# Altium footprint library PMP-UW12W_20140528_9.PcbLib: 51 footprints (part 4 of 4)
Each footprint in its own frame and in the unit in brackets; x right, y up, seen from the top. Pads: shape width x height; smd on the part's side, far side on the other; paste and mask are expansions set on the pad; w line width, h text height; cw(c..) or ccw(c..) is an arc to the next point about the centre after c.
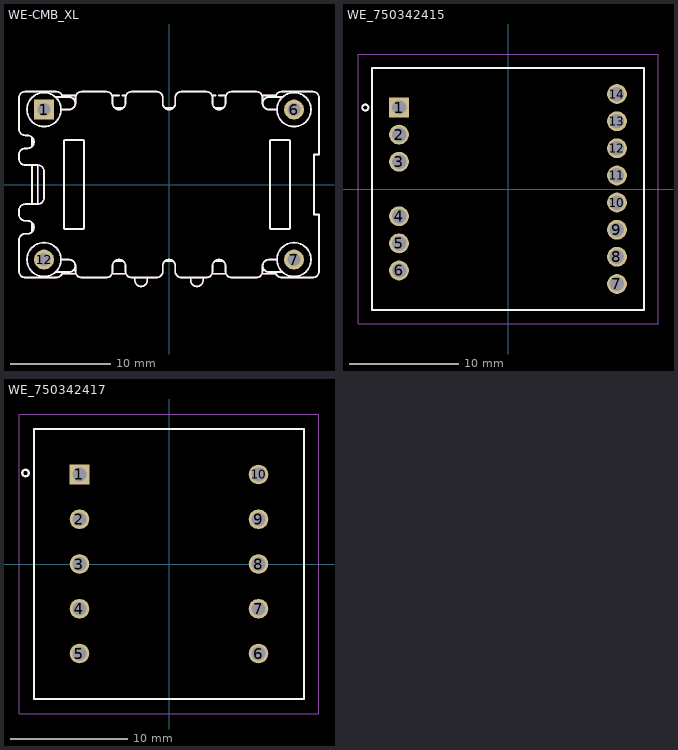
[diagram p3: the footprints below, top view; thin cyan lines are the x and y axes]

## WE-CMB_XL [mm] "Wurth"
height 35
pads (4):
  rect 2x2 hole 1.3: 1(-12.5,7.5)
  round 2 hole 1.3: 6(12.5,7.5) 7(12.5,-7.5) 12(-12.5,-7.5)
Top Overlay:
  drawing of 411 lines, arcs and shapes, not listed
Mechanical 5:
  drawing of 419 lines, arcs and shapes, not listed
  text ".Designator" at -1.9,-0.525 h1.02
3D body: height 8, standoff 3, extent -15.25,-10.499 15.249,10.499
3D body: height 35, standoff 6, extent -15,-7.2 14.941,7.2
3D body: height 3, standoff 0, extent 10.074,-4.426 12.075,4.451
3D body: height 3, standoff 0, extent -10.501,-4.426 -8.5,4.451

## WE_750342415 [mm] "TRANSFOERMER, TH, 14-PIN"
height 16
pads (14):
  rect 1.82x1.82 / inner round 1.82 / far side rect 1.82x1.82 hole 1.32: 1(-10,7.48)
  round 1.82 hole 1.32: 2(-10,4.99) 3(-10,2.5) 4(-10,-2.5) 5(-10,-4.99) 6(-10,-7.48) 7(10,-8.715) 8(10,-6.225) 9(10,-3.735) 10(10,-1.245) 11(10,1.245) 12(10,3.735) 13(10,6.225) 14(10,8.715)
Top Overlay:
  circle w0.178: c-13.1,7.48 r0.279
  lines w0.178: -12.5,-11.1 12.5,-11.1 12.5,11.1 -12.5,11.1 -12.5,-11.1
  text ".Designator" at -1.041,12.065 h1.02
Bottom Overlay:
  lines w0.178: -12.5,-11.1 -12.5,-10.054 ; -12.5,-9.264 -12.5,-7.054 ; -12.5,-6.264 -12.5,-4.054 ; -12.5,-3.237 -12.5,-1.027 ; -12.5,-0.237 -12.5,1.973 ; -12.5,2.763 -12.5,4.973 ; -12.5,5.763 -12.5,7.973 ; -12.5,8.89 -12.5,11.1 -10.287,11.1 ; -10.894,-11.1 -8.627,-11.1 ; -9.5,11.1 -7.287,11.1 ; -7.894,-11.1 -5.627,-11.1 ; -6.5,11.1 -4.287,11.1 ; -4.894,-11.1 -2.627,-11.1 ; -3.5,11.1 -1.287,11.1 ; -1.894,-11.1 0.373,-11.1 ; -0.5,11.1 1.713,11.1 ; 1.106,-11.1 3.373,-11.1 ; 2.528,11.1 4.741,11.1 ; 4.106,-11.1 6.373,-11.1 ; 5.529,11.1 7.742,11.1 ; 7.106,-11.1 9.373,-11.1 ; 8.528,11.1 10.741,11.1 ; 10.233,-11.1 12.5,-11.1 12.5,-8.609 ; 12.5,-8.176 12.5,-5.685 ; 12.5,-5.176 12.5,-2.685 ; 12.5,-2.176 12.5,0.315 ; 12.5,0.824 12.5,3.315 ; 12.5,3.862 12.5,6.353 ; 12.5,6.862 12.5,9.353 ; 12.5,9.862 12.5,11.1
Mechanical 5:
  circle w0.127: c-13.1,7.48 r0.279
  lines w0.127: -12.5,-11.1 12.5,-11.1 12.5,11.1 -12.5,11.1 -12.5,-11.1
  text ".Designator" at -1.524,-0.508 h1.02
Mechanical 15:
  lines w0.05: -13.77,-12.37 -13.77,12.37 13.77,12.37 13.77,-12.37 -13.77,-12.37
Mechanical 17:
  text "LEAD LENGTH MAX: 4:00 MM" at -12.065,9.652 h1
3D body: height 16, standoff 0, extent -12.5,-11.1 12.5,11.1

## WE_750342417 [mm] "TRANSFOERMER, TH, 10-PIN"
height 17.53
pads (10):
  rect 1.67x1.67 / inner round 1.67 / far side rect 1.67x1.67 hole 1.17: 1(-7.62,7.62)
  round 1.67 hole 1.17: 2(-7.62,3.81) 3(-7.62,0) 4(-7.62,-3.81) 5(-7.62,-7.62) 6(7.62,-7.62) 7(7.62,-3.81) 8(7.62,0) 9(7.62,3.81) 10(7.62,7.62)
Top Layer:
  lines w0.178: 11.5,9 11.5,11.5
Top Overlay:
  circle w0.178: c-12.217,7.747 r0.279
  lines w0.178: -11.5,-11.5 -11.5,11.5 11.5,11.5 11.5,-11.5 -11.5,-11.5
  text ".Designator" at -1.524,12 h1.02
Bottom Overlay:
  lines w0.178: -11.5,-9.599 -11.5,-11.5 -9,-11.5 ; -11.5,-9.099 -11.5,-6.599 ; -11.5,-6.099 -11.5,-3.599 ; -11.5,-3.127 -11.5,-0.627 ; -11.5,-0.127 -11.5,2.373 ; -11.5,2.873 -11.5,5.373 ; -11.5,5.873 -11.5,8.373 ; -11.5,9 -11.5,11.5 -9,11.5 ; -8.5,-11.5 -6,-11.5 ; -8.5,11.5 -6,11.5 ; -5.5,-11.5 -3,-11.5 ; -5.5,11.5 -3,11.5 ; -2.5,-11.5 0,-11.5 ; -2.5,11.5 0,11.5 ; 0.5,-11.5 3,-11.5 ; 0.5,11.5 3,11.5 ; 3.5,-11.5 6,-11.5 ; 3.5,11.5 6,11.5 ; 6.5,-11.5 9,-11.5 ; 6.5,11.5 9,11.5 ; 9.5,-11.5 11.5,-11.5 11.5,-9.472 ; 9.5,11.5 11.5,11.5 11.5,9 ; 11.5,-8.972 11.5,-6.472 ; 11.5,-5.972 11.5,-3.472 ; 11.5,-3 11.5,-0.5 ; 11.5,0 11.5,2.5 ; 11.5,3 11.5,5.5 ; 11.5,6 11.5,8.5
Mechanical 5:
  circle w0.127: c-12.217,7.747 r0.279
  lines w0.127: -11.5,-11.5 -11.5,11.5 11.5,11.5 11.5,-11.5 -11.5,-11.5
  text ".Designator" at -1.524,-0.508 h1.02
Mechanical 15:
  lines w0.05: -12.77,-12.77 12.77,-12.77 12.77,12.77 -12.77,12.77 -12.77,-12.77
Mechanical 17:
  text "LEAD LENGTH MAX: 4:00 MM" at -11.684,9.652 h1
3D body: height 17.53, standoff 0, extent -11.5,-11.5 11.5,11.5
